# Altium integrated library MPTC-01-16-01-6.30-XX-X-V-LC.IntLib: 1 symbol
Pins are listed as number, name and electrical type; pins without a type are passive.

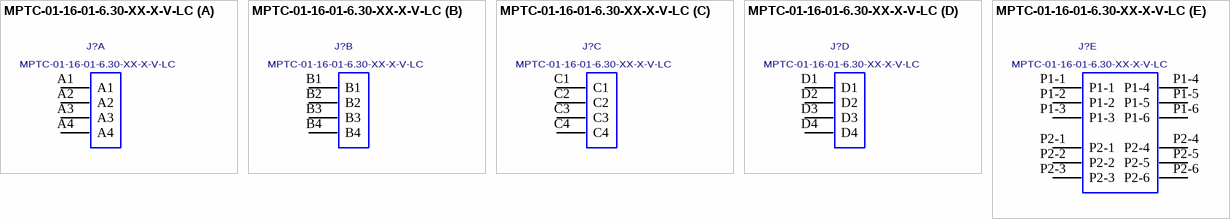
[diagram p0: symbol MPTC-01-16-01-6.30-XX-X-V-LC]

## MPTC-01-16-01-6.30-XX-X-V-LC
designator J?
VERTICAL POWER TERMINAL, 16 SIGNAL PINS, 2 POWER PINS.; MANUFACTURER: SAMTEC
footprint MPTC-01-16-01-6.30-XX-X-V-LC
part A pins: A1, A2, A3, A4
part B pins: B1, B2, B3, B4
part C pins: C1, C2, C3, C4
part D pins: D1, D2, D3, D4
part E pins: P1-1, P1-2, P1-3, P1-4, P1-5, P1-6, P2-1, P2-2, P2-3, P2-4, P2-5, P2-6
